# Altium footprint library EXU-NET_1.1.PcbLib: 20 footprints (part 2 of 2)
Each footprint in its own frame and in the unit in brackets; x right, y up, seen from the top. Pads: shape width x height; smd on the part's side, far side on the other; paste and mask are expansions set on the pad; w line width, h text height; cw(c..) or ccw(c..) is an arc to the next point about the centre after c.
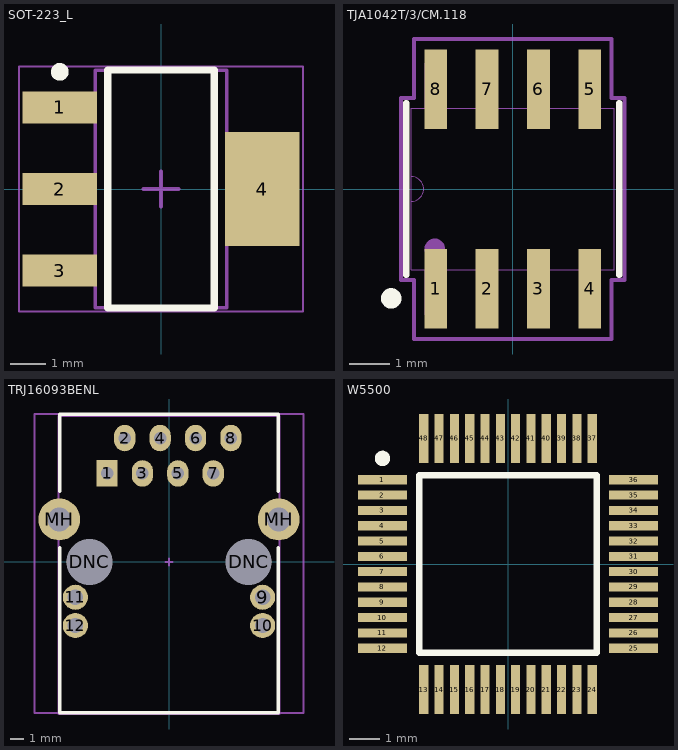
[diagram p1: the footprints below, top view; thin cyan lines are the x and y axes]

## SOT-223_L [mm]
pads (4):
  rect 2.1x0.9 smd: 1(-2.85,2.3) 2(-2.85,0) 3(-2.85,-2.3)
  rect 2.1x3.2 smd: 4(2.85,0)
Top Overlay:
  circle w0.25: c-2.85,3.3 r0.125
  lines w0.2: -1.5,-3.35 -1.5,3.35 1.5,3.35 1.5,-3.35 -1.5,-3.35
Mechanical 13:
  lines w0.1: -1.85,-3.35 -1.85,3.35 1.85,3.35 1.85,-3.35 -1.85,-3.35
Mechanical 15:
  lines w0.05: -4,-3.45 -4,3.45 4,3.45 4,-3.45 -4,-3.45
  lines w0.1: -0.5,0 0.5,0 ; 0,-0.5 0,0.5
3D body: height 1.8, standoff 0.02, extent -1.85,-3.35 1.85,3.35

## TJA1042T/3/CM.118 [mm]
pads (8):
  rect 0.558x1.97 smd paste+0 mask+0: 1(-1.905,-2.464) 2(-0.635,-2.464) 3(0.635,-2.464) 4(1.905,-2.464) 5(1.905,2.464) 6(0.635,2.464) 7(-0.635,2.464) 8(-1.905,2.464)
Top Overlay:
  circle w0.254: c-3,-2.7 r0.125
  lines w0.152: -2.629,-2.121 -2.629,2.121 ; 2.629,-2.121 2.629,2.121
Mechanical 1:
  lines w0.1: -2.756,-2.248 -2.438,-2.248 -2.438,-3.703 2.438,-3.703 2.438,-2.248 2.756,-2.248 2.756,2.248 2.438,2.248 2.438,3.703 -2.438,3.703 -2.438,2.248 -2.756,2.248 -2.756,-2.248
Top Assembly:
  circle w0.254: c-1.925,-1.475 r0.125
  lines w0.025: -2.502,-0.305 ccw(c-2.502,0) -2.502,0.305 ; -2.502,-1.994 2.502,-1.994 2.502,1.994 -2.502,1.994 -2.502,-1.994 ; -2.159,-3.099 -1.651,-3.099 -1.651,-1.994 -2.159,-1.994 -2.159,-3.099 ; -2.159,1.994 -2.159,3.099 -1.651,3.099 -1.651,1.994 -2.159,1.994 ; -0.889,-3.099 -0.381,-3.099 -0.381,-1.994 -0.889,-1.994 -0.889,-3.099 ; -0.889,1.994 -0.889,3.099 -0.381,3.099 -0.381,1.994 -0.889,1.994 ; 0.381,-3.099 0.889,-3.099 0.889,-1.994 0.381,-1.994 0.381,-3.099 ; 0.381,1.994 0.381,3.099 0.889,3.099 0.889,1.994 0.381,1.994 ; 1.651,-3.099 1.651,-1.994 2.159,-1.994 2.159,-3.099 1.651,-3.099 ; 1.651,1.994 1.651,3.099 2.159,3.099 2.159,1.994 1.651,1.994
Mechanical 13:
  lines w0.025: -2.502,-0.305 ccw(c-2.502,0) -2.502,0.305 ; -2.502,-1.994 2.502,-1.994 2.502,1.994 -2.502,1.994 -2.502,-1.994 ; -2.159,-3.099 -1.651,-3.099 -1.651,-1.994 -2.159,-1.994 -2.159,-3.099 ; -2.159,1.994 -2.159,3.099 -1.651,3.099 -1.651,1.994 -2.159,1.994 ; -0.889,-3.099 -0.381,-3.099 -0.381,-1.994 -0.889,-1.994 -0.889,-3.099 ; -0.889,1.994 -0.889,3.099 -0.381,3.099 -0.381,1.994 -0.889,1.994 ; 0.381,-3.099 0.889,-3.099 0.889,-1.994 0.381,-1.994 0.381,-3.099 ; 0.381,1.994 0.381,3.099 0.889,3.099 0.889,1.994 0.381,1.994 ; 1.651,-3.099 2.159,-3.099 2.159,-1.994 1.651,-1.994 1.651,-3.099 ; 1.651,1.994 1.651,3.099 2.159,3.099 2.159,1.994 1.651,1.994
3D body "R_8_ADI.step": height 1.76, standoff 0, extent -2.502,-3.099 2.502,3.099

## TRJ16093BENL [mm]
pads (16):
  rect 1.525x1.9 hole 0.9: 1(-4.445,6.35)
  oval 1.525x1.9 hole 0.9: 2(-3.175,8.89) 3(-1.905,6.35) 4(-0.635,8.89) 5(0.635,6.35) 6(1.905,8.89) 7(3.175,6.35) 8(4.445,8.89)
  round 1.8 hole 1.1: 9(6.725,-2.54) 10(6.725,-4.57) 11(-6.725,-2.54) 12(-6.725,-4.57)
  round 3.251 hole 3.3 unplated: DNC(-5.715,0) DNC(5.715,0)
  round 3 hole 1.7: MH(-7.874,3.048) MH(7.874,3.048)
Top Overlay:
  lines w0.254: -7.855,1.016 -7.855,-10.846 7.855,-10.846 7.855,1.016 ; -7.855,5.08 -7.855,10.592 7.855,10.592 7.855,5.08
Mechanical 13:
  lines w0.127: -7.94,-10.92 7.94,-10.92 7.94,10.48 -7.94,10.48 -7.94,-10.92
Mechanical 15:
  lines w0.127: -0.254,0 0.254,0 ; 0,-0.254 0,0.254 ; -9.652,-10.846 -9.652,10.617 9.652,10.617 9.652,-10.846 -9.652,-10.846
3D body "TRJ16093BENL (2).stp": height 14.6, standoff -2.2, extent -7.999,-10.914 8.001,10.586

## W5500 [mm]
pads (48):
  rect 1.6x0.3 smd: 1(-4.1,2.75) 2(-4.1,2.25) 3(-4.1,1.75) 4(-4.1,1.25) 5(-4.1,0.75) 6(-4.1,0.25) 7(-4.1,-0.25) 8(-4.1,-0.75) 9(-4.1,-1.25) 10(-4.1,-1.75) 11(-4.1,-2.25) 12(-4.1,-2.75) 25(4.1,-2.75) 26(4.1,-2.25) 27(4.1,-1.75) 28(4.1,-1.25) 29(4.1,-0.75) 30(4.1,-0.25) 31(4.1,0.25) 32(4.1,0.75) 33(4.1,1.25) 34(4.1,1.75) 35(4.1,2.25) 36(4.1,2.75)
  rect 0.3x1.6 smd: 13(-2.75,-4.1) 14(-2.25,-4.1) 15(-1.75,-4.1) 16(-1.25,-4.1) 17(-0.75,-4.1) 18(-0.25,-4.1) 19(0.25,-4.1) 20(0.75,-4.1) 21(1.25,-4.1) 22(1.75,-4.1) 23(2.25,-4.1) 24(2.75,-4.1) 37(2.75,4.1) 38(2.25,4.1) 39(1.75,4.1) 40(1.25,4.1) 41(0.75,4.1) 42(0.25,4.1) 43(-0.25,4.1) 44(-0.75,4.1) 45(-1.25,4.1) 46(-1.75,4.1) 47(-2.25,4.1) 48(-2.75,4.1)
Top Overlay:
  circle w0.25: c-4.1,3.45 r0.125
  lines w0.2: -2.9,-2.9 -2.9,2.9 2.9,2.9 2.9,-2.9 -2.9,-2.9
3D body "User Library-WIZNET_W5500.STEP": height 1.6, standoff 0, extent -4.5,-4.5 4.5,4.5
